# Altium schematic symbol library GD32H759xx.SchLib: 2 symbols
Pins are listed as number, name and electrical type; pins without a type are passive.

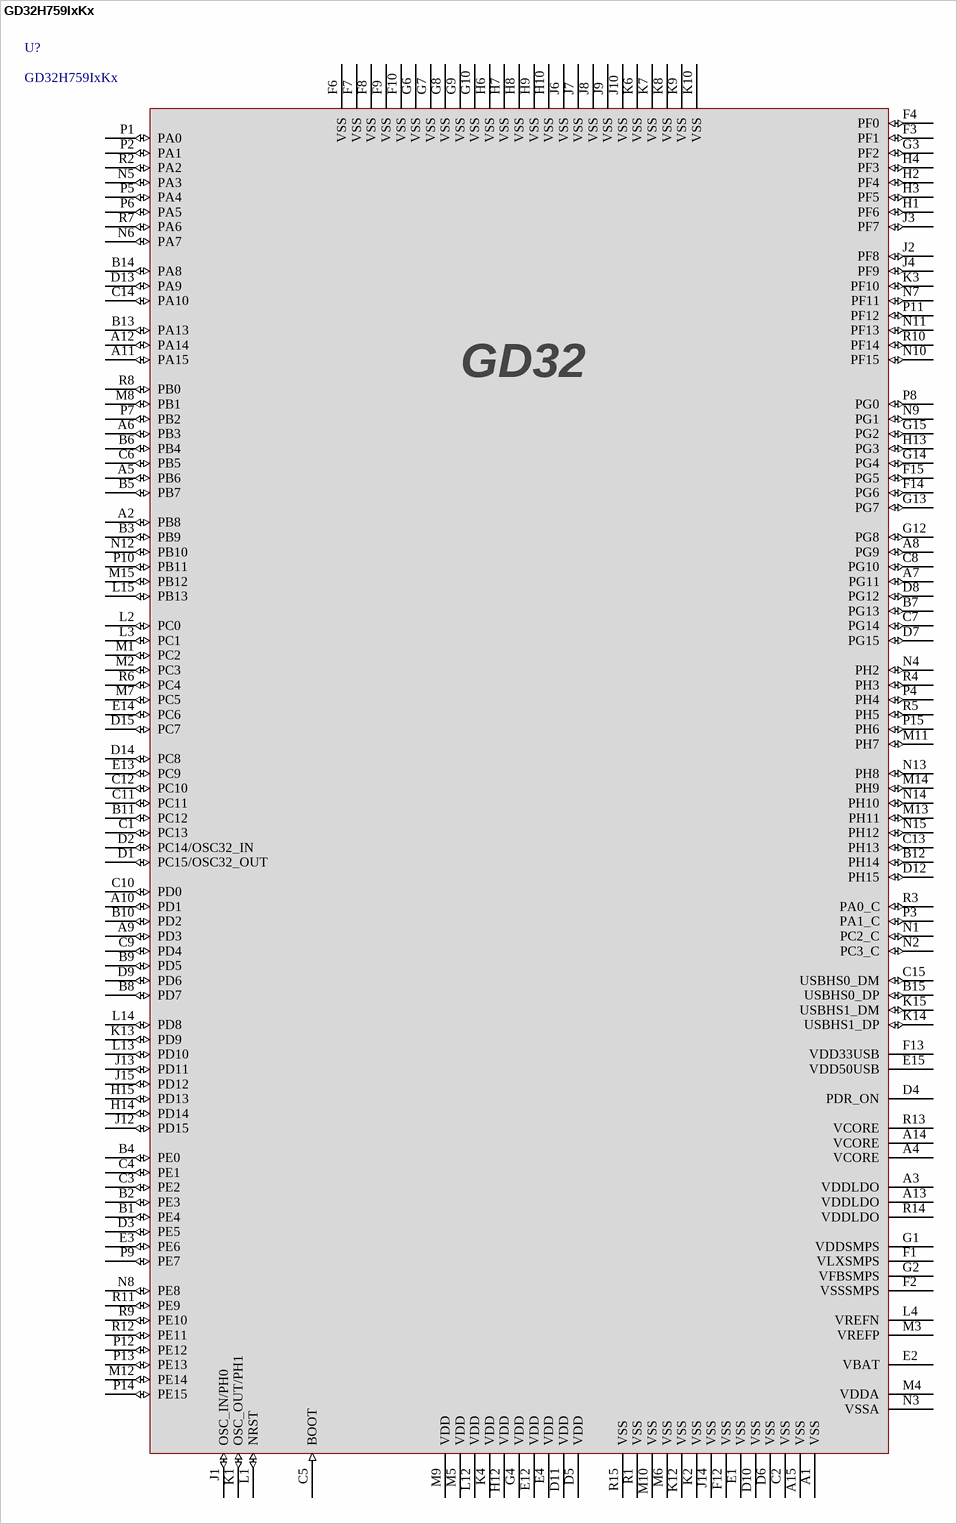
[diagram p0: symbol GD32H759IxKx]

## GD32H759IxKx
designator U?
footprint BGA176_10x10X0.68
pins: A1 VSS (power), A2 PB8 (io), A3 VDDLDO (power), A4 VCORE (power), A5 PB6 (io), A6 PB3 (io), A7 PG11 (io), A8 PG9 (io), A9 PD3 (io), A10 PD1 (io), A11 PA15 (io), A12 PA14 (io), A13 VDDLDO (power), A14 VCORE (power), A15 VSS (power), B1 PE4 (io), B2 PE3 (io), B3 PB9 (io), B4 PE0 (io), B5 PB7 (io), B6 PB4 (io), B7 PG13 (io), B8 PD7 (io), B9 PD5 (io), B10 PD2 (io), B11 PC12 (io), B12 PH14 (io), B13 PA13 (io), B14 PA8 (io), B15 USBHS0_DP (io), C1 PC13 (io), C2 VSS (power), C3 PE2 (io), C4 PE1 (io), C5 BOOT (in), C6 PB5 (io), C7 PG14 (io), C8 PG10 (io), C9 PD4 (io), C10 PD0 (io), C11 PC11 (io), C12 PC10 (io), C13 PH13 (io), C14 PA10 (io), C15 USBHS0_DM (io), D1 PC15/OSC32_OUT (io), D2 PC14/OSC32_IN (io), D3 PE5 (io), D4 PDR_ON (power), D5 VDD (power), D6 VSS (power), D7 PG15 (io), D8 PG12 (io), D9 PD6 (io), D10 VSS (power), D11 VDD (power), D12 PH15 (io), D13 PA9 (io), D14 PC8 (io), D15 PC7 (io), E1 VSS (power), E2 VBAT (power), E3 PE6 (io), E4 VDD (power), E12 VDD (power), E13 PC9 (io), E14 PC6 (io), E15 VDD50USB (power), F1 VLXSMPS (power), F2 VSSSMPS (power), F3 PF1 (io), F4 PF0 (io), F6 VSS (power), F7 VSS (power), F8 VSS (power), F9 VSS (power), F10 VSS (power), F12 VSS (power), F13 VDD33USB (power), F14 PG6 (io), F15 PG5 (io), G1 VDDSMPS (power), G2 VFBSMPS (power), G3 PF2 (io), G4 VDD (power), G6 VSS (power), G7 VSS (power), G8 VSS (power), G9 VSS (power), G10 VSS (power), G12 PG8 (io), G13 PG7 (io), G14 PG4 (io), G15 PG2 (io), H1 PF6 (io), H2 PF4 (io), H3 PF5 (io), H4 PF3 (io), H6 VSS (power), H7 VSS (power), H8 VSS (power), H9 VSS (power), H10 VSS (power), H12 VDD (power), H13 PG3 (io), H14 PD14 (io), H15 PD13 (io), J1 OSC_IN/PH0 (io), J2 PF8 (io), J3 PF7 (io), J4 PF9 (io), J6 VSS (power), J7 VSS (power), J8 VSS (power), J9 VSS (power), J10 VSS (power), J12 PD15 (io), J13 PD11 (io), J14 VSS (power), J15 PD12 (io), K1 OSC_OUT/PH1 (io), K2 VSS (power), K3 PF10 (io), K4 VDD (power), K6 VSS (power), K7 VSS (power), K8 VSS (power), K9 VSS (power), K10 VSS (power), K12 VSS (power), K13 PD9 (io), K14 USBHS1_DP (io), K15 USBHS1_DM (io), L1 NRST (io), L2 PC0 (io), L3 PC1 (io), L4 VREFN (power), L12 VDD (power), L13 PD10 (io), L14 PD8 (io), L15 PB13 (io), M1 PC2 (io), M2 PC3 (io), M3 VREFP (power), M4 VDDA (power), M5 VDD (power), M6 VSS (power), M7 PC5 (io), M8 PB1 (io), M9 VDD (power), M10 VSS (power), M11 PH7 (io), M12 PE14 (io), M13 PH11 (io), M14 PH9 (io), M15 PB12 (io), N1 PC2_C (io), N2 PC3_C (io), N3 VSSA (power), N4 PH2 (io), N5 PA3 (io), N6 PA7 (io), N7 PF11 (io), N8 PE8 (io), N9 PG1 (io), N10 PF15 (io), N11 PF13 (io), N12 PB10 (io), N13 PH8 (io), N14 PH10 (io), N15 PH12 (io), P1 PA0 (io), P2 PA1 (io), P3 PA1_C (io), P4 PH4 (io), P5 PA4 (io), P6 PA5 (io), P7 PB2 (io), P8 PG0 (io), P9 PE7 (io), P10 PB11 (io), P11 PF12 (io), P12 PE12 (io), P13 PE13 (io), P14 PE15 (io), P15 PH6 (io), R1 VSS (power), R2 PA2 (io), R3 PA0_C (io), R4 PH3 (io), R5 PH5 (io), R6 PC4 (io), R7 PA6 (io), R8 PB0 (io), R9 PE10 (io), R10 PF14 (io), R11 PE9 (io), R12 PE11 (io), R13 VCORE (power), R14 VDDLDO (power), R15 VSS (power)

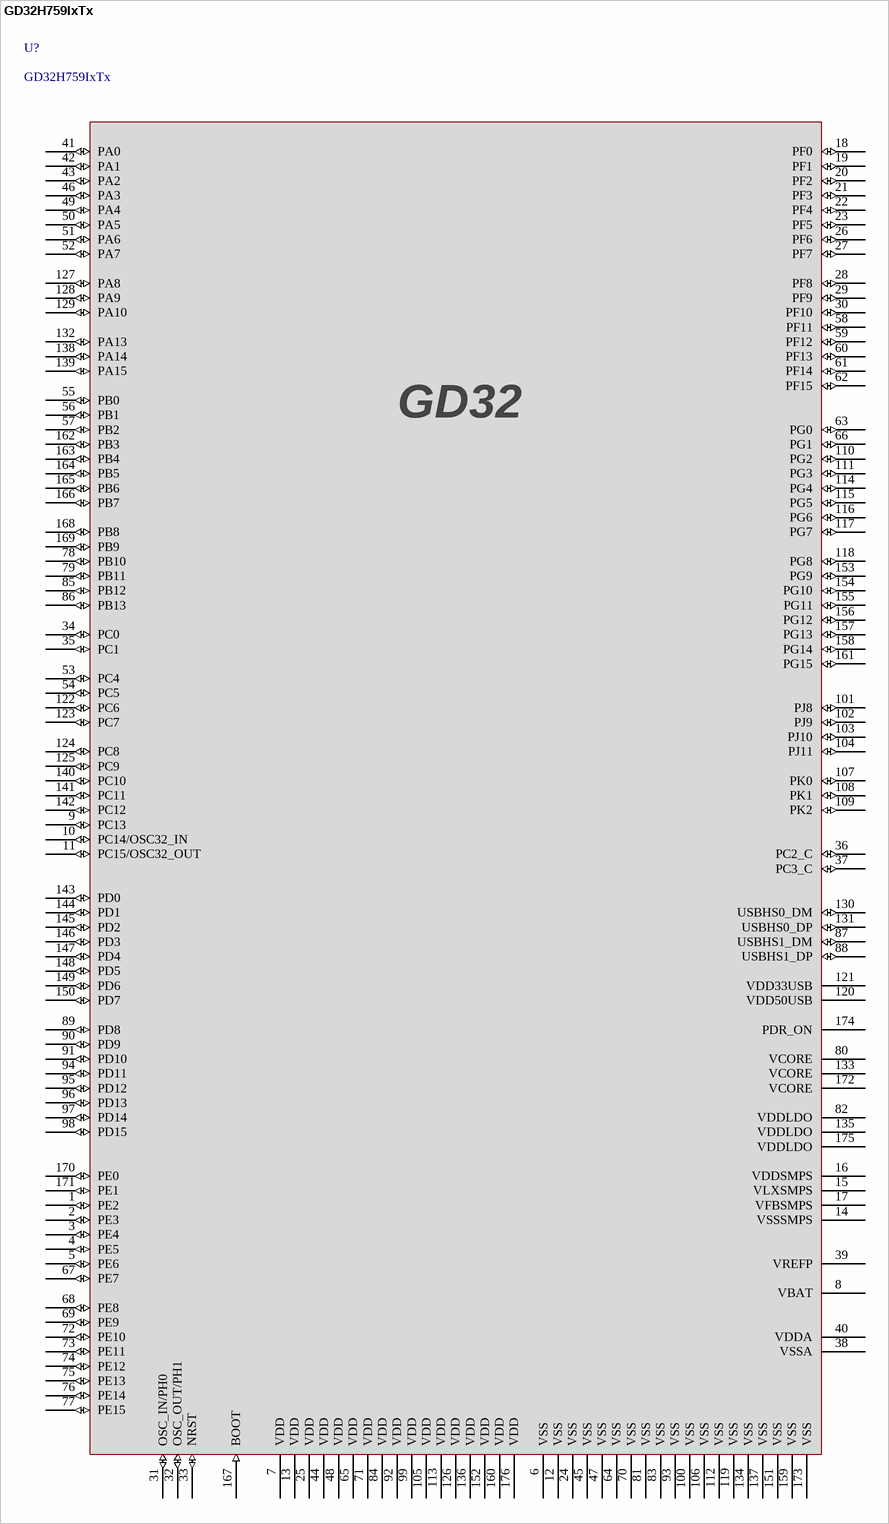
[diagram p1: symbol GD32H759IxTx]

## GD32H759IxTx
designator U?
footprint LQFP176_24x24X1.6
pins: 1 PE2 (io), 2 PE3 (io), 3 PE4 (io), 4 PE5 (io), 5 PE6 (io), 6 VSS (power), 7 VDD (power), 8 VBAT (power), 9 PC13 (io), 10 PC14/OSC32_IN (io), 11 PC15/OSC32_OUT (io), 12 VSS (power), 13 VDD (power), 14 VSSSMPS (power), 15 VLXSMPS (power), 16 VDDSMPS (power), 17 VFBSMPS (power), 18 PF0 (io), 19 PF1 (io), 20 PF2 (io), 21 PF3 (io), 22 PF4 (io), 23 PF5 (io), 24 VSS (power), 25 VDD (power), 26 PF6 (io), 27 PF7 (io), 28 PF8 (io), 29 PF9 (io), 30 PF10 (io), 31 OSC_IN/PH0 (io), 32 OSC_OUT/PH1 (io), 33 NRST (io), 34 PC0 (io), 35 PC1 (io), 36 PC2_C (io), 37 PC3_C (io), 38 VSSA (power), 39 VREFP (power), 40 VDDA (power), 41 PA0 (io), 42 PA1 (io), 43 PA2 (io), 44 VDD (power), 45 VSS (power), 46 PA3 (io), 47 VSS (power), 48 VDD (power), 49 PA4 (io), 50 PA5 (io), 51 PA6 (io), 52 PA7 (io), 53 PC4 (io), 54 PC5 (io), 55 PB0 (io), 56 PB1 (io), 57 PB2 (io), 58 PF11 (io), 59 PF12 (io), 60 PF13 (io), 61 PF14 (io), 62 PF15 (io), 63 PG0 (io), 64 VSS (power), 65 VDD (power), 66 PG1 (io), 67 PE7 (io), 68 PE8 (io), 69 PE9 (io), 70 VSS (power), 71 VDD (power), 72 PE10 (io), 73 PE11 (io), 74 PE12 (io), 75 PE13 (io), 76 PE14 (io), 77 PE15 (io), 78 PB10 (io), 79 PB11 (io), 80 VCORE (power), 81 VSS (power), 82 VDDLDO (power), 83 VSS (power), 84 VDD (power), 85 PB12 (io), 86 PB13 (io), 87 USBHS1_DM (io), 88 USBHS1_DP (io), 89 PD8 (io), 90 PD9 (io), 91 PD10 (io), 92 VDD (power), 93 VSS (power), 94 PD11 (io), 95 PD12 (io), 96 PD13 (io), 97 PD14 (io), 98 PD15 (io), 99 VDD (power), 100 VSS (power), 101 PJ8 (io), 102 PJ9 (io), 103 PJ10 (io), 104 PJ11 (io), 105 VDD (power), 106 VSS (power), 107 PK0 (io), 108 PK1 (io), 109 PK2 (io), 110 PG2 (io), 111 PG3 (io), 112 VSS (power), 113 VDD (power), 114 PG4 (io), 115 PG5 (io), 116 PG6 (io), 117 PG7 (io), 118 PG8 (io), 119 VSS (power), 120 VDD50USB (power), 121 VDD33USB (power), 122 PC6 (io), 123 PC7 (io), 124 PC8 (io), 125 PC9 (io), 126 VDD (power), 127 PA8 (io), 128 PA9 (io), 129 PA10 (io), 130 USBHS0_DM (io), 131 USBHS0_DP (io), 132 PA13 (io), 133 VCORE (power), 134 VSS (power), 135 VDDLDO (power), 136 VDD (power), 137 VSS (power), 138 PA14 (io), 139 PA15 (io), 140 PC10 (io), 141 PC11 (io), 142 PC12 (io), 143 PD0 (io), 144 PD1 (io), 145 PD2 (io), 146 PD3 (io), 147 PD4 (io), 148 PD5 (io), 149 PD6 (io), 150 PD7 (io), 151 VSS (power), 152 VDD (power), 153 PG9 (io), 154 PG10 (io), 155 PG11 (io), 156 PG12 (io), 157 PG13 (io), 158 PG14 (io), 159 VSS (power), 160 VDD (power), 161 PG15 (io), 162 PB3 (io), 163 PB4 (io), 164 PB5 (io), 165 PB6 (io), 166 PB7 (io), 167 BOOT (in), 168 PB8 (io), 169 PB9 (io), 170 PE0 (io), 171 PE1 (io), 172 VCORE (power), 173 VSS (power), 174 PDR_ON (power), 175 VDDLDO (power), 176 VDD (power)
